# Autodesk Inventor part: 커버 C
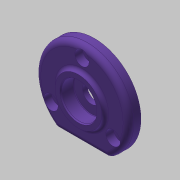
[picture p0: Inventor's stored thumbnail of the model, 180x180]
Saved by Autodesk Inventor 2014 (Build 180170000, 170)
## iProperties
Created: 2020-04
Part Number: 커버 C
Material: 알루미늄 6061
Document SubType Name: Modeling
Designer: mduedu
Density: 1 g/cm^3
Appearance: 보라색
Author: mduedu
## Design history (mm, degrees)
sketch "스케치1"
  geometry: C1 r 26 at (0, 0); 1 further point
  constraints: 1 centre point, 1 coincident
  dimensions: "d0" = 52 diameter of C1
extrude "돌출1" new body sketch "스케치1" distance "d1" = 7; taper "d2" = 0 deg
sketch "스케치2"
  geometry: L1 (-14.62, -21.5)-(14.62, -21.5); A1 r 26 centre (0, 0) between (-14.62, -21.5) and (14.62, -21.5) reference; 1 further point
  constraints: 2 end point, 2 point on circle, 1 horizontal
  dimensions: "d3" = 21.5 distance from line of L1 point (0, 0)
extrude "돌출2" cut sketch "스케치2" stored distance "d4" = 7; taper "d5" = 0 deg
sketch "스케치6"
  geometry: C1 r 13 at (0, 0); 1 further point
  constraints: 1 centre point, 1 coincident
  dimensions: "d29" = 26 diameter of C1
extrude "돌출5" join sketch "스케치6" distance "d30" = 2; taper "d31" = 0 deg
fillet "모깎기1" dims "d6" = 3
fillet "모깎기2" dims "d7" = 3
fillet "모깎기4" dims "d33" = 2
sketch "스케치3" dims "d8" = 40
  geometry: 3 further points
  constraints: 2 vertical alignment, 1 coincident, 2 other
hole "구멍1" sketch "스케치3" at (0, 20) diameter "d9" = 4.5; stored, may be unused: countersink angle "d13" = 90 deg, drill point angle "d15" = 118 deg; dims "d10" = 6, "d11" = 8, "d12" = 4.4, "d14" = 8
sketch "스케치4"
  geometry: C1 r 14 at (0, 0); 1 further point
  constraints: 1 centre point, 1 coincident
  dimensions: "d19" = 28 diameter of C1
extrude "돌출3" join sketch "스케치4" distance "d20" = 4; taper "d21" = 0 deg
sketch "스케치5"
  geometry: C1 r 12 at (0, 0); 1 further point
  constraints: 1 centre point, 1 coincident
  dimensions: "d22" = 24 diameter of C1
extrude "돌출4" cut sketch "스케치5" distance "d23" = 3; taper "d24" = 0 deg
fillet "모깎기3" dims "d25" = 3
chamfer "모따기1" distance "d26" = 0.5; stored, may be unused: second distance "d27" = 2, angle "d28" = 45 deg
sketch "스케치7"
  geometry: 2 further points
  constraints: 1 coincident
hole "구멍2" sketch "스케치7" at (0, 0) diameter "d34" = 10; stored, may be unused: countersink angle "d38" = 90 deg, drill point angle "d40" = 118 deg; dims "d35" = 6, "d36" = 20, "d37" = 7.3, "d39" = 8
fillet "모깎기5" dims "d41" = 0.3
chamfer "모따기2" distance "d42" = 0.7; stored, may be unused: second distance "d43" = 2, angle "d44" = 30 deg
node "솔리드1"
pattern_circular "원형 패턴1" dims angle "d17" = 360 deg
node "투영된 루프1"
